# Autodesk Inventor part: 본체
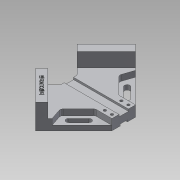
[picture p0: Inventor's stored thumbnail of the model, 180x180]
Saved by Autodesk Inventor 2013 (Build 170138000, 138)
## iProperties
Created: 2019-04
Part Number: 본체
Material: 알루미늄 6061
Document SubType Name: Modeling
Designer: Administrator
Mass: 603.737 g
Surface Area: 426.536 cm^2
Volume: 222.781 cm^3
Density: 2.71 g/cm^3
Author: Administrator
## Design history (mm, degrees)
sketch "스케치1"
  geometry: L1 (84.853, 0)-(0, -84.853); L2 (0, -84.853)-(-84.853, 0); L3 (-84.853, 0)-(-35.355, 49.497); L4 (0, 84.853)-(35.355, 49.497); L5 (0, 84.853)-(0, -84.853); L6 (35.355, 49.497)-(0, 14.142); L7 (0, 14.142)-(-35.355, 49.497); L8 (-35.355, 49.497)-(0, 84.853); L9 (0, 84.853)-(35.355, 49.497); L10 (-35.355, 49.497)-(0, 84.853); L11 (35.355, 49.497)-(84.853, 0); L12 (-20, -64.853)-(20, -64.853); L13 (-14.005, 28.147)-(14.005, 28.147); 4 further points
  constraints: 26 end point, 4 point on line, 2 horizontal, 2 vertical alignment, 1 coincident, 1 midpoint, 1 vertical, 18 other
  dimensions: "d0" = 120 distance of L4.start L1.start; "d1" = 50 distance of L4.end L6.end; "d2" = 20 distance from line of L1.end L12; "d3" = 93 distance between parallel lines of L12 L13
extrude "돌출1" new body sketch "스케치1" distance "d4" = 18; taper "d5" = 0 deg
sketch "스케치2"
  geometry: L1 (14.005, 28.147)-(-14.005, 28.147) reference; L2 (-20, -64.853)-(20, -64.853) reference; L3 (-8, 28.147)-(8, 28.147); L4 (8, 28.147)-(8, -64.853); L5 (8, -64.853)-(-8, -64.853); L6 (-8, -64.853)-(-8, 28.147); 3 further points
  constraints: 8 end point, 3 midpoint, 2 parallel, 2 point on line, 1 horizontal, 1 perpendicular, 1 vertical alignment
  dimensions: "d6" = 16 distance of L3.start L3.end; "d8" = 93 distance of L3.end L4.end (derived)
extrude "돌출2" cut sketch "스케치2" distance "d9" = 3.5; taper "d10" = 0 deg
sketch "스케치3"
  geometry: L1 (-14.005, 28.147)-(14.005, 28.147) reference; L2 (20, -64.853)-(-20, -64.853) reference; L3 (6, -64.853)-(-6, -64.853); L4 (-6, -64.853)-(-6, 28.147); L5 (-6, 28.147)-(6, 28.147); L6 (6, 28.147)-(6, -64.853); 2 further points
  constraints: 8 end point, 2 midpoint, 2 parallel, 1 collinear, 1 horizontal, 1 perpendicular, 1 point on line
  dimensions: "d11" = 12 distance between parallel lines of L6 L4
extrude "돌출3" cut sketch "스케치3" distance "d14" = 3; taper "d15" = 0 deg
sketch "스케치4"
  geometry: L1 (20, -64.853)-(84.853, 0) reference; L2 (84.853, 0)-(35.355, 49.497) reference; L3 (-35.355, 49.497)-(-84.853, 0) reference; L4 (-14.005, 28.147)-(-35.355, 49.497) reference; L5 (-84.853, 0)-(-20, -64.853) reference; L6 (-35.355, 49.497)-(-84.853, 0); L7 (-84.853, 0)-(-74.246, -10.607); L8 (-74.246, -10.607)-(-24.749, 38.891); L9 (-24.749, 38.891)-(-35.355, 49.497); L10 (35.355, 49.497)-(84.853, 0); L11 (84.853, 0)-(74.246, -10.607); L12 (74.246, -10.607)-(24.749, 38.891); L13 (24.749, 38.891)-(35.355, 49.497); 1 further point
  constraints: 16 end point, 4 parallel, 3 perpendicular
  dimensions: "d16" = 15 distance between parallel lines of L6 L8; "d18" = 15 distance between parallel lines of L2 L12
extrude "돌출4" join sketch "스케치4" distance "d19" = 24; taper "d20" = 0 deg
sketch "스케치6"
  geometry: L1 (-74.246, -10.607)-(-20, -64.853) reference; L2 (-8, -64.853)-(-8, 28.147) reference; L3 (74.246, -10.607)-(24.749, 38.891) reference; L4 (24.749, 38.891)-(14.005, 28.147) reference; L5 (14.005, 28.147)-(8, 28.147) reference; L6 (8, 28.147)-(8, -64.853) reference; L7 (8, -64.853)-(20, -64.853) reference; L8 (20, -64.853)-(74.246, -10.607) reference; L9 (-70.711, -14.142)-(-49.497, -7.071); L10 (-49.497, -7.071)-(-20, -36.569); L11 (-20, -36.569)-(-20, -64.853); L12 (-35.355, 49.497)-(-84.853, 0) reference; L13 (-46.315, -18.031)-(-29.345, -35.002); L14 (-52.679, -24.395)-(-35.709, -41.366); A1 r 4.5 centre (-49.497, -21.213) between (-46.315, -18.031) and (-52.679, -24.395); A2 r 4.5 centre (-32.527, -38.184) between (-35.709, -41.366) and (-29.345, -35.002); 1 further point
  constraints: 10 end point, 4 point on circle, 4 tangent, 2 centre point, 1 equal radius, 1 parallel, 1 perpendicular, 1 point on line
  dimensions: "d21" = 20 distance between parallel lines of L1 L10; "d22" = 20 distance from line of L9.start L12; "d23" = 30 distance from line of L9.end L12; "d24" = 10 distance from line of L1 A1.centre; "d25" = 24 distance of A2.centre A1.centre; "d26" = 9 distance between parallel lines of L13 L14; "d27" = 40 distance from line of A1.centre L12; "d28" = 10 distance from line of L1 A2.centre
  node "투영된 루프1"
extrude "돌출5" cut sketch "스케치6" distance "d29" = 10; taper "d30" = 0 deg
extrude "돌출6" cut sketch "스케치6" stored distance "d31" = 10; taper "d32" = 0 deg
sketch "스케치8"
  geometry: L1 (-6, -64.853)-(-20, -64.853) reference; 3 further points
  constraints: 1 vertical alignment
  dimensions: "d36" = 14 horizontal distance of point (0, 0) point (-14, -58.853); "d37" = 6 distance from line of L1 point (-14, -58.853); "d38" = 12 distance of point (-14, -58.853) point (-14, -46.853)
hole "구멍1" sketch "스케치8" at (-14, -58.853), (-14, -46.853) diameter "d39" = 4.5; stored, may be unused: countersink angle "d43" = 90 deg, drill point angle "d45" = 118 deg; dims "d40" = 6, "d41" = 8, "d42" = 10, "d44" = 8
sketch "스케치10"
  geometry: L1 (-35.355, 49.497)-(-84.853, 0) reference; L2 (-24.749, 38.891)-(-35.355, 49.497) reference; 2 further points
  constraints: 1 other
  dimensions: "d50" = 7.5 distance from line of point (-54.801, 19.445) L1; "d51" = 35 distance from line of L2 point (-54.801, 19.445)
fillet "모깎기1" dims "d48" = 5
fillet "모깎기2" dims "d49" = 5
feature "엠보싱1" dims "d0" = 120, "d1" = 50, "d2" = 20, "d3" = 93, "d52" = 0.5, "d53" = 0
node "솔리드1"
mirror "대칭1"
mirror "대칭2"
